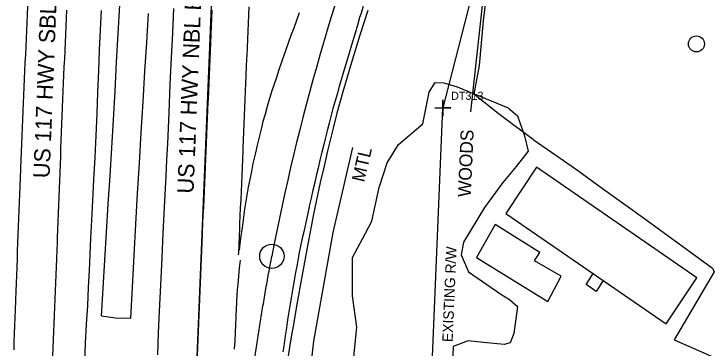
# Model space of a CAD drawing. Extents: x 2262665 to 2270527, y 505476 to 514960.
# Drawn here: x 2266302.1 to 2266517.9, y 511264.1 to 511367.1 of the extents above; entities that cross this region are included whole.
import ezdxf

# ---------------------------------------------------------------- set-up
doc = ezdxf.new("R2010")
doc.units = 0
for name, color, linetype in [('Exist Building', 7, 'Continuous'), ('Exist Guardrail', 7, 'Continuous'), ('Exist Guardrail Text', 7, 'Continuous'), ('Exist Horizontal Alignment', 7, 'Continuous'), ('Exist Other Culture Area Outline', 7, 'Continuous'), ('Exist Other Culture Fence Line', 7, 'Continuous'), ('Exist Property Corner CELL', 7, 'Continuous'), ('Exist Property Corner Cogo Number', 7, 'Continuous'), ('Exist Right of Way Control of Access Line', 7, 'Continuous'), ('Exist Right of Way Line', 7, 'Continuous'), ('Exist Right of Way Line Text', 7, 'Continuous'), ('Exist Roads EOP', 7, 'Continuous'), ('Exist Roads EOP Text', 7, 'Continuous'), ('Exist Roads EOT', 7, 'Continuous'), ('Exist Roads Soil', 7, 'Continuous'), ('Exist Structure Minor Paved Ditch or Gutter', 7, 'Continuous'), ('Exist Utilities Other Pole CELL', 7, 'Continuous'), ('Exist Vegetation Woods Line', 7, 'Continuous'), ('Exist Vegetation Woods Line Text', 7, 'Continuous')]:
    doc.layers.add(name, color=color, linetype=linetype)

msp = doc.modelspace()

# ---------------------------------------------------------------- linework, layer by layer
at = {"layer": 'Exist Building'}
for points in [[(2266512.68, 511285.72), (2266463.26, 511319.86), (2266453.76, 511305.53), (2266503.15, 511271.54)], [(2266470.79, 511286.19), (2266462.59, 511290.93), (2266464.19, 511293.55), (2266450.52, 511302.17), (2266444.69, 511291.95), (2266466.72, 511278.42)]]:
    msp.add_lwpolyline(points, close=True, dxfattribs=at)
at = {"layer": 'Exist Guardrail'}
msp.add_lwpolyline([(2266406.46, 511325.92), (2266400.4, 511299.72), (2266394.43, 511266.2), (2266390.64, 511233.16), (2266387.86, 511199.31), (2266386.05, 511177.01)], dxfattribs=at)
at = {"layer": 'Exist Horizontal Alignment'}
msp.add_line((2266320.5, 510340.11), (2266385.32, 511909.14), dxfattribs=at)
msp.add_circle((2266381.63, 511292.36), 3.75, dxfattribs=at)
msp.add_circle((2266381.63, 511292.36), 3.75, dxfattribs=at)
msp.add_arc((2267054.57, 511164.4), 685, 147.91012, 169.234, dxfattribs=at)
msp.add_spline([(2266363.55, 511093.37), (2266363.67, 511096.07), (2266363.78, 511098.77), (2266363.9, 511101.47), (2266364.01, 511104.17), (2266364.12, 511106.87), (2266364.24, 511109.57), (2266364.36, 511112.27), (2266364.47, 511114.97), (2266364.59, 511117.67), (2266364.71, 511120.37), (2266364.83, 511123.07), (2266364.96, 511125.77), (2266365.08, 511128.47), (2266365.21, 511131.17), (2266365.33, 511133.87), (2266365.47, 511136.57), (2266365.6, 511139.27), (2266365.73, 511141.97), (2266365.87, 511144.67), (2266366.01, 511147.37), (2266366.16, 511150.07), (2266366.3, 511152.77), (2266366.45, 511155.46), (2266366.6, 511158.16), (2266366.76, 511160.86), (2266366.92, 511163.56), (2266367.08, 511166.26), (2266367.25, 511168.95), (2266367.42, 511171.65), (2266367.6, 511174.35), (2266367.78, 511177.04), (2266367.96, 511179.74), (2266368.15, 511182.44), (2266368.35, 511185.13), (2266368.55, 511187.83), (2266368.75, 511190.52), (2266368.96, 511193.22), (2266369.17, 511195.91), (2266369.39, 511198.61), (2266369.62, 511201.3), (2266369.85, 511203.99), (2266370.09, 511206.68), (2266370.33, 511209.38), (2266370.58, 511212.07), (2266370.84, 511214.76), (2266371.1, 511217.45), (2266371.37, 511220.14), (2266371.64, 511222.83), (2266371.92, 511225.51), (2266372.21, 511228.2), (2266372.51, 511230.89), (2266372.81, 511233.57), (2266373.12, 511236.26), (2266373.44, 511238.94), (2266373.77, 511241.62), (2266374.1, 511244.31), (2266374.45, 511246.99), (2266374.8, 511249.67), (2266375.16, 511252.35), (2266375.52, 511255.02), (2266375.9, 511257.7), (2266376.28, 511260.38), (2266376.68, 511263.05), (2266377.08, 511265.72), (2266377.49, 511268.39), (2266377.91, 511271.06), (2266378.34, 511273.73), (2266378.78, 511276.4), (2266379.23, 511279.06), (2266379.69, 511281.73), (2266380.16, 511284.39), (2266380.64, 511287.05), (2266381.13, 511289.71), (2266381.63, 511292.36)], degree=3, dxfattribs=at)
at = {"layer": 'Exist Other Culture Area Outline'}
msp.add_lwpolyline([(2266483.73, 511284.91), (2266481.6, 511281.52), (2266478.49, 511283.69), (2266480.67, 511287.02)], dxfattribs=at)
at = {"layer": 'Exist Other Culture Fence Line'}
msp.add_lwpolyline([(2266477.02, 511460.51), (2266467.89, 511439.49), (2266460.66, 511424.72), (2266454.49, 511408.54), (2266449.44, 511389.89), (2266446.67, 511371.6), (2266442.88, 511336.94)], dxfattribs=at)
at = {"layer": 'Exist Property Corner CELL'}
msp.add_line((2266434.35, 511338.09), (2266434.35, 511338.09), dxfattribs=at)
msp.add_lwpolyline([(2266431.85, 511338.09), (2266436.85, 511338.09), (2266434.35, 511338.09), (2266434.35, 511340.59), (2266434.35, 511335.59)], dxfattribs=at)
at = {"layer": 'Exist Right of Way Control of Access Line'}
msp.add_line((2266413.07, 510822.98), (2266434.35, 511338.09), dxfattribs=at)
at = {"layer": 'Exist Right of Way Line'}
msp.add_line((2266449.28, 511396.54), (2266434.35, 511338.09), dxfattribs=at)
at = {"layer": 'Exist Roads EOP'}
for points in [[(2266323.96, 511260.07), (2266324.23, 511265.52), (2266324.54, 511271.31), (2266324.85, 511277.14), (2266325.14, 511282.68), (2266325.39, 511287.93), (2266325.62, 511292.89), (2266325.85, 511297.96), (2266326.12, 511303.51), (2266326.43, 511309.55), (2266326.77, 511316.07), (2266327.12, 511322.83), (2266327.44, 511329.57), (2266327.73, 511336.28), (2266327.99, 511342.97), (2266328.25, 511349.55), (2266328.53, 511355.95), (2266328.82, 511362.16), (2266329.14, 511368.18)], [(2266351.35, 511368.77), (2266350.98, 511361.21), (2266350.59, 511353.54), (2266350.19, 511345.45), (2266349.82, 511336.6), (2266349.42, 511327.09), (2266349.18, 511322.13), (2266348.92, 511317.02), (2266348.43, 511307.45), (2266348.04, 511299.45), (2266347.68, 511291.86), (2266347.26, 511283.49), (2266346.87, 511275.43), (2266346.61, 511268.77), (2266346.35, 511261.93)], [(2266411.17, 511368.14), (2266408.73, 511360.53), (2266406.16, 511352.1), (2266403.54, 511343.09), (2266401.67, 511336.44), (2266400.48, 511331.88), (2266398.8, 511324.86), (2266397.71, 511320.15), (2266396.56, 511315.1), (2266394.5, 511305.38), (2266392.7, 511296.08), (2266390.95, 511286.65), (2266389.23, 511276.97), (2266388.38, 511271.98), (2266387.53, 511266.89), (2266386.7, 511261.69)]]:
    msp.add_lwpolyline(points, dxfattribs=at)
at = {"layer": 'Exist Roads EOT'}
for points in [[(2266302.14, 511263.47), (2266302.23, 511265.97), (2266302.32, 511268.47), (2266302.41, 511270.97), (2266302.5, 511273.46), (2266302.59, 511275.96), (2266302.68, 511278.46), (2266302.7, 511279.04), (2266302.8, 511281.53), (2266302.89, 511284.03), (2266302.99, 511286.53), (2266303.08, 511289.03), (2266303.18, 511291.52), (2266303.27, 511294.02), (2266303.37, 511296.52), (2266303.46, 511299.01), (2266303.56, 511301.51), (2266303.66, 511304.01), (2266303.75, 511306.51), (2266303.85, 511309), (2266303.94, 511311.5), (2266304.04, 511314), (2266304.13, 511316.5), (2266304.23, 511318.99), (2266304.25, 511319.57), (2266304.36, 511322.07), (2266304.46, 511324.57), (2266304.57, 511327.07), (2266304.68, 511329.56), (2266304.78, 511332.06), (2266304.89, 511334.56), (2266305, 511337.05), (2266305.1, 511339.55), (2266305.21, 511342.05), (2266305.31, 511344.55), (2266305.42, 511347.04), (2266305.53, 511349.54), (2266305.63, 511352.04), (2266305.74, 511354.53), (2266305.85, 511356.97), (2266305.96, 511359.46), (2266306.07, 511361.96), (2266306.19, 511364.46), (2266306.3, 511366.95), (2266306.42, 511369.45)], [(2266318.31, 511368.24), (2266318.2, 511365.74), (2266318.09, 511363.24), (2266317.99, 511360.74), (2266317.88, 511358.25), (2266317.77, 511355.75), (2266317.66, 511353.25), (2266317.55, 511350.76), (2266317.44, 511348.26), (2266317.33, 511345.76), (2266317.22, 511343.26), (2266317.11, 511340.77), (2266317, 511338.27), (2266316.99, 511338.09), (2266316.9, 511335.59), (2266316.8, 511333.1), (2266316.71, 511330.6), (2266316.62, 511328.1), (2266316.52, 511325.6), (2266316.43, 511323.11), (2266316.33, 511320.61), (2266316.24, 511318.11), (2266316.15, 511315.61), (2266316.05, 511313.12), (2266315.96, 511310.62), (2266315.87, 511308.12), (2266315.77, 511305.62), (2266315.68, 511303.13), (2266315.58, 511300.63), (2266315.49, 511298.13), (2266315.43, 511296.63), (2266315.34, 511294.14), (2266315.24, 511291.64), (2266315.14, 511289.14), (2266315.04, 511286.64), (2266314.94, 511284.15), (2266314.84, 511281.65), (2266314.74, 511279.15), (2266314.65, 511276.66), (2266314.55, 511274.16), (2266314.45, 511271.66), (2266314.35, 511269.16), (2266314.25, 511266.67), (2266314.15, 511264.17), (2266314.05, 511261.67)], [(2266363.09, 511368.21), (2266362.99, 511365.71), (2266362.89, 511363.21), (2266362.79, 511360.72), (2266362.69, 511358.22), (2266362.58, 511355.72), (2266362.48, 511353.22), (2266362.38, 511350.73), (2266362.28, 511348.23), (2266362.18, 511345.73), (2266362.08, 511343.23), (2266361.98, 511340.74), (2266361.94, 511339.86), (2266361.83, 511337.36), (2266361.72, 511334.87), (2266361.61, 511332.37), (2266361.5, 511329.87), (2266361.39, 511327.38), (2266361.28, 511324.88), (2266361.17, 511322.38), (2266361.06, 511319.89), (2266360.95, 511317.39), (2266360.84, 511314.89), (2266360.73, 511312.4), (2266360.62, 511309.9), (2266360.51, 511307.4), (2266360.4, 511304.91), (2266360.29, 511302.41), (2266360.18, 511299.91), (2266360.15, 511299.15), (2266360.04, 511296.65), (2266359.94, 511294.16), (2266359.84, 511291.66), (2266359.73, 511289.16), (2266359.63, 511286.67), (2266359.52, 511284.17), (2266359.42, 511281.67), (2266359.31, 511279.18), (2266359.21, 511276.68), (2266359.11, 511274.18), (2266359, 511271.69), (2266358.9, 511269.19), (2266358.79, 511266.69), (2266358.69, 511264.2), (2266358.59, 511261.7)], [(2266374.52, 511369.25), (2266374.42, 511366.75), (2266374.32, 511364.25), (2266374.21, 511361.75), (2266374.11, 511359.26), (2266374, 511356.76), (2266373.9, 511354.26), (2266373.86, 511353.24), (2266373.76, 511350.74), (2266373.65, 511348.25), (2266373.55, 511345.75), (2266373.45, 511343.25), (2266373.34, 511340.75), (2266373.24, 511338.26), (2266373.14, 511335.76), (2266373.03, 511333.26), (2266372.93, 511330.77), (2266372.83, 511328.27), (2266372.72, 511325.77), (2266372.68, 511324.79), (2266372.57, 511322.3), (2266372.46, 511319.8), (2266372.35, 511317.3), (2266372.24, 511314.81), (2266372.13, 511312.31), (2266372.02, 511309.82), (2266371.91, 511307.32), (2266371.79, 511304.82), (2266371.68, 511302.33), (2266371.62, 511300.91), (2266371.51, 511298.41), (2266371.41, 511295.92), (2266371.3, 511293.42), (2266371.27, 511292.84)], [(2266390.06, 511367.43), (2266389.21, 511365.08), (2266388.36, 511362.73), (2266387.51, 511360.38), (2266386.66, 511358.03), (2266385.81, 511355.68), (2266385.4, 511354.54), (2266384.6, 511352.18), (2266383.81, 511349.81), (2266383.01, 511347.44), (2266382.21, 511345.07), (2266381.64, 511343.36), (2266380.94, 511340.97), (2266380.23, 511338.57), (2266379.53, 511336.17), (2266378.87, 511333.96), (2266378.3, 511331.52), (2266377.72, 511329.09), (2266377.14, 511326.66), (2266376.57, 511324.23), (2266375.99, 511321.8), (2266375.79, 511320.97), (2266375.31, 511318.52), (2266374.82, 511316.07), (2266374.34, 511313.66), (2266373.94, 511311.19), (2266373.54, 511308.72), (2266373.14, 511306.26), (2266373.11, 511306.04), (2266372.78, 511303.57), (2266372.44, 511301.09), (2266372.11, 511298.61), (2266371.78, 511296.14), (2266371.53, 511294.27)], [(2266409.77, 511369.35), (2266409.01, 511366.97), (2266408.69, 511365.97), (2266407.98, 511363.57), (2266407.28, 511361.17), (2266406.57, 511358.78), (2266405.86, 511356.38), (2266405.15, 511353.98), (2266404.45, 511351.59), (2266403.74, 511349.19), (2266403.03, 511346.79), (2266402.32, 511344.39), (2266401.82, 511342.68), (2266401.14, 511340.27), (2266400.47, 511337.87), (2266399.91, 511335.87), (2266399.29, 511333.45), (2266398.68, 511331.02), (2266398.06, 511328.6), (2266397.61, 511326.86), (2266397.04, 511324.42), (2266396.46, 511321.99), (2266395.88, 511319.56), (2266395.31, 511317.13), (2266394.84, 511315.15), (2266394.28, 511312.72), (2266393.72, 511310.28), (2266393.16, 511307.85), (2266393.11, 511307.6), (2266392.58, 511305.16), (2266392.06, 511302.72), (2266391.54, 511300.34), (2266391.02, 511297.9), (2266390.5, 511295.45), (2266389.98, 511293.01), (2266389.83, 511292.3), (2266389.39, 511289.85), (2266388.96, 511287.39), (2266388.52, 511284.93), (2266388.08, 511282.47), (2266387.64, 511280.01), (2266387.24, 511277.74), (2266386.87, 511275.27), (2266386.5, 511272.8), (2266386.13, 511270.33), (2266385.75, 511267.85), (2266385.38, 511265.38), (2266385.01, 511262.91)], [(2266371.84, 511291.16), (2266371.59, 511288.67), (2266371.35, 511286.18), (2266371.1, 511283.7), (2266371.03, 511283.02), (2266370.87, 511280.52), (2266370.71, 511278.03), (2266370.59, 511276.23), (2266370.48, 511273.73), (2266370.38, 511271.23), (2266370.27, 511268.74), (2266370.17, 511266.24), (2266370.06, 511263.74)]]:
    msp.add_lwpolyline(points, dxfattribs=at)
at = {"layer": 'Exist Roads Soil'}
for points in [[(2266477.55, 511455.85), (2266473.55, 511448.2), (2266469.55, 511440.54), (2266465.55, 511432.89), (2266462.1, 511425.11), (2266458.64, 511417.33), (2266456.36, 511410.62), (2266454.08, 511403.91), (2266452.21, 511396.62), (2266450.34, 511389.33), (2266448.29, 511377.62), (2266446.76, 511364.93), (2266446.13, 511358.07), (2266445.5, 511351.2), (2266443.88, 511342.39)], [(2266462.17, 511328.39), (2266456.77, 511332.41), (2266451.37, 511336.43), (2266443.88, 511342.39)], [(2266462.17, 511328.39), (2266469.21, 511323.48), (2266476.25, 511318.58), (2266483.13, 511313.6), (2266490, 511308.63), (2266496.88, 511303.65), (2266503.75, 511298.67), (2266510.62, 511293.7), (2266517.5, 511288.72), (2266518.03, 511287.58), (2266513.9, 511280.59), (2266509.78, 511273.6), (2266505.65, 511266.6), (2266514.75, 511262.54), (2266523.84, 511258.47)]]:
    msp.add_lwpolyline(points, dxfattribs=at)
at = {"layer": 'Exist Structure Minor Paved Ditch or Gutter'}
msp.add_lwpolyline([(2266343.51, 511367.18), (2266342.94, 511358.29), (2266342.37, 511349.39), (2266341.81, 511339.96), (2266341.25, 511330.53), (2266340.69, 511321.11), (2266340.13, 511311.68), (2266339.57, 511302.25), (2266339.07, 511292.56), (2266338.57, 511282.87), (2266338.06, 511273.18), (2266333.43, 511273.25), (2266329.1, 511273.84), (2266329.63, 511282.5), (2266330.16, 511291.15), (2266330.68, 511299.8), (2266331.21, 511308.46), (2266331.74, 511317.11), (2266332.27, 511325.76), (2266332.79, 511334.42), (2266333.29, 511343.29), (2266333.78, 511352.17), (2266334.28, 511361.04), (2266334.77, 511369.92)], dxfattribs=at)
at = {"layer": 'Exist Utilities Other Pole CELL'}
msp.add_circle((2266512.52, 511357.83), 2.46, dxfattribs=at)
at = {"layer": 'Exist Vegetation Woods Line'}
msp.add_lwpolyline([(2266406.76, 511260.32), (2266407.8, 511270.52), (2266406.46, 511280.12), (2266406.53, 511291.94), (2266409.54, 511297.73), (2266412.41, 511303.15), (2266414.71, 511313.6), (2266417.18, 511321.16), (2266420.68, 511326.86), (2266428.2, 511333.19), (2266430.14, 511343), (2266431.99, 511345.97), (2266434.68, 511345.87), (2266438.72, 511344.59), (2266454.47, 511338.16), (2266457.35, 511335.68), (2266459.54, 511329.52), (2266460.62, 511324.77), (2266456.92, 511320.04), (2266452.88, 511315.08), (2266447.23, 511307.37), (2266440.67, 511296.68), (2266439.98, 511292.78), (2266442.28, 511287.56), (2266452.22, 511280.62), (2266454.86, 511279.04), (2266457.38, 511276.89), (2266456.22, 511268.57), (2266455.12, 511265.68), (2266453.28, 511265.15), (2266446.87, 511265.76), (2266442.14, 511266.3), (2266437.56, 511264.54), (2266437.26, 511256.29)], dxfattribs=at)

# ---------------------------------------------------------------- texts
at = {"layer": 'Exist Guardrail Text'}
msp.add_text('MTL', height=4, rotation=76.9638, dxfattribs=at).set_placement((2266410.1, 511315.01))
at = {"layer": 'Exist Property Corner Cogo Number'}
msp.add_text('DT313', height=2.5, dxfattribs=at).set_placement((2266436.85, 511340.59))
at = {"layer": 'Exist Right of Way Line Text'}
msp.add_text('EXISTING R/W', height=3.2, rotation=87.5983, dxfattribs=at).set_placement((2266437.35, 511265.84))
at = {"layer": 'Exist Roads EOP Text'}
for s, p in [('US 117 HWY SBL BST VARIES', (2266313.09, 511316.35)), ('US 117 HWY NBL BST VARIES', (2266357.47, 511311.61))]:
    msp.add_text(s, height=5, rotation=87.7086, dxfattribs=at).set_placement(p)
at = {"layer": 'Exist Vegetation Woods Line Text'}
msp.add_text('WOODS', height=4, rotation=87.4803, dxfattribs=at).set_placement((2266442.95, 511310.55))

doc.saveas('drawing.dxf')
